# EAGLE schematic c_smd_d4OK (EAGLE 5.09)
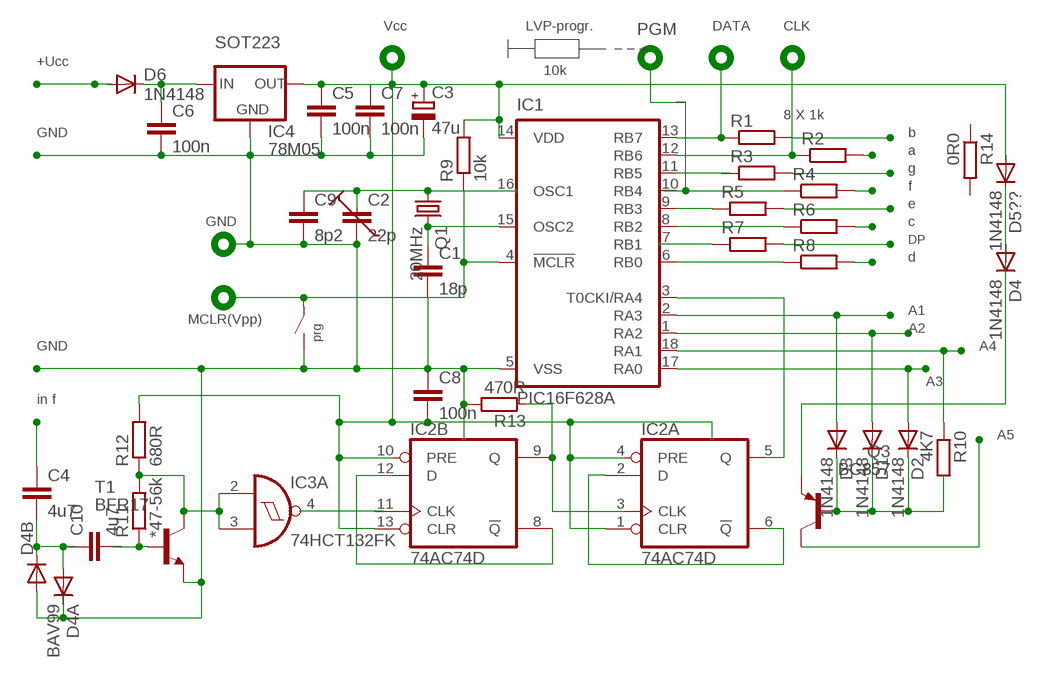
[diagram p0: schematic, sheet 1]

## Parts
C1  18p  C-EUC0805  [C0805]
C2  22p  C-EUC0805  [C0805]
C3  47u  CPOL-EU085CS-1AR  [085CS_1AR]
C4  4u7  C-EUC0805  [C0805]
C5  100n  C-EUC0805  [C0805]
C6  100n  C-EUC0805  [C0805]
C7  100n  C-EUC0805  [C0805]
C8  100n  C-EUC0805  [C0805]
C9  8p2  C-EUC0805  [C0805]
C10  4u7  C-EUC0805  [C0805]
D1  1N4148  [DO35-10]
D2  1N4148  [DO35-10]
D3  1N4148  [DO35-10]
D4  1N4148  [DO35-10]
D4A  BAV99  1N4148  [DO35-10]
D4B  1N4148  [DO35-10]
D5??  1N4148  [DO35-10]
D6  1N4148  [DO35-10]
IC1  PIC16F628A  PIC16C84P  [DIL18]
IC2  74AC74D  74ACT74D  [SO14]
IC3  74HCT132FK  [LCC20]
IC4  78M05  78LXX  [78LXX]
Q1  20MHz  CRYSTALHC49U70  [HC49U70]
Q3  BC857  BC857ALT1SMD  [SOT23-BEC]
R1  R-EU_R0805  [R0805]
R2  R-EU_R0805  [R0805]
R3  R-EU_R0805  [R0805]
R4  R-EU_R0805  [R0805]
R5  R-EU_R0805  [R0805]
R6  R-EU_R0805  [R0805]
R7  R-EU_R0805  [R0805]
R8  R-EU_R0805  [R0805]
R9  10k  R-EU_R0805  [R0805]
R10  4K7  R-EU_R0805  [R0805]
R11  *47-56k  R-EU_R0805  [R0805]
R12  680R  R-EU_R0805  [R0805]
R13  470R  R-EU_R0805  [R0805]
R14  0R0  R-EU_R0805  [R0805]
T1  BFR17  BF199  [TO92]

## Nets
N$1: IC3.4(A:O)
N$2: IC1.4(!MCLR) R9.1
N$3: R11.1 T1.1(B)
N$4: C2.1 C9.1 IC1.16(OSC1) Q1.1
N$5: C1.1 IC1.15(OSC2) Q1.2
N$6: C4.2 D4B.C
N$7: D3.A IC1.2(RA3)
N$8: D1.A IC1.1(RA2)
N$9: IC1.18(RA1) R10.1
N$10: D2.A IC1.17(RA0)
N$11: IC1.3(T0CKI/RA4) IC2.5(A:Q)
N$12: IC2.2(A:D) IC2.6(A:!Q)
N$13: IC3.2(A:I0) R11.2 R12.1 T1.3(C)
N$14: Q3.C
N$15: IC2.8(B:!Q) IC2.12(B:D)
N$16: IC2.3(A:CLK) IC2.9(B:Q)
N$17: C3.+ C5.1 C7.1 C8.2 IC1.14(VDD) IC2.1(A:CLR) IC2.4(A:PRE) IC2.10(B:PRE) IC2.13(B:CLR) IC4.OUT R9.2 R12.2
N$18: C1.2 C2.2 C3.- C5.2 C6.2 C8.1 C9.2 D4B.A IC1.5(VSS) IC4.GND R13.2 T1.2(E)
N$19: Q3.E
N$20: D1.C D2.C D3.C Q3.B R10.2
N$21: IC1.13(RB7) R1.1
N$22: IC1.12(RB6) R2.1
N$23: R2.2
N$24: R1.2
N$25: R3.2
N$26: R4.1
N$27: R4.2
N$28: R5.2
N$29: R6.2
N$30: R8.2
N$31: R7.2
N$32: IC1.9(RB3) R5.1
N$33: IC1.8(RB2) R6.1
N$34: IC1.7(RB1) R7.1
N$35: IC1.6(RB0) R8.1
N$36: IC1.11(RB5) R3.1
N$37: D4A.A
N$39: C4.1
N$41: C6.1 D6.C IC4.IN
Unconnected: C7.2 C10.1 C10.2 D4.A D4.C D4A.C D5??.A D5??.C D6.A IC1.10(RB4) IC2.11(B:CLK) IC3.3(A:I1) IC3.6(B:I0) IC3.8(B:I1) IC3.9(B:O) IC3.12(C:O) IC3.13(C:I0) IC3.14(C:I1) IC3.16(D:O) IC3.18(D:I0) IC3.19(D:I1) R13.1 R14.1 R14.2

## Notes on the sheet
- Vcc | LVP-progr. | DATA | CLK
- PGM
- SOT223
- +Ucc
- 10k
- 8 X 1k
- GND | b
- a
- g
- f
- e
- GND | c
- DP
- d
- A1
- MCLR(Vpp)
- A2
- prg
- GND | A4
- A3
- in f
- A5

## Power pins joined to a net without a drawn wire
GND: IC2.7(P:GND) IC3.10(P:GND)
VCC: IC2.14(P:VCC) IC3.20(P:VCC)

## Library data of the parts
C1 C2 C4-C10 = rcl:C-EU: CAPACITOR, European symbol
C3 = rcl:CPOL-EU: POLARIZED CAPACITOR, European symbol
D1-D4 D4A D4B D5?? D6 = diode:1N4148: DIODE
IC1 = microchip-3:PIC16C84: MICROCONTROLLER EPROM/ROM-based
IC2 = 74xx-eu:74*74: Dual D type positive edge triggered FLIP FLOP, preset and clear
IC3 = 74xx-eu:74*132: Quad 2-input NAND schmitt trigger
IC4 = v-reg:78LXX: VOLTAGE REGULATOR
Q1 = crystal:CRYSTAL: CRYSTAL
Q3 = transistor-pnp:BC857*: PNP Transistror
R1-R14 = rcl:R-EU_: RESISTOR, European symbol
T1 = transistor-npn:BF199*: NPN Transistor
